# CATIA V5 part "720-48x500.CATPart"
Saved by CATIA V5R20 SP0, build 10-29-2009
Part number: 720-48x500
Definition: NONE
Nomenclature: 720-48x500
Source: Unknown
Description: 720-48x500
Bounding box of the stored display mesh (mm): x 0 to 500, y -24 to 24, z -24 to 24
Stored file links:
  C:\Users\Utente\Desktop\IO LAVORO\3D X SITO CF\X SITO\720\720-48x500.CATPart
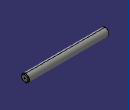
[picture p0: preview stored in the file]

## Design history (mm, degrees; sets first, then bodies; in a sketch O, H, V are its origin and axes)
Body1 "720-48x500" (main body)
  Solid1: solid without history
